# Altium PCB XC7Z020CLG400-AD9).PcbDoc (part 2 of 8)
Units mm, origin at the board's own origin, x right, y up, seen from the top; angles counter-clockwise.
Board outline 38 x 38 mm, 14 copper layers (Top Layer, GND02, ART03, PWR04, ART05, GND06, ART07, ART08, PWR09, ART10, GND11, ART12, PWR13, Bottom Layer); 276 components, 302 nets, 1684 pads, 1576 vias.
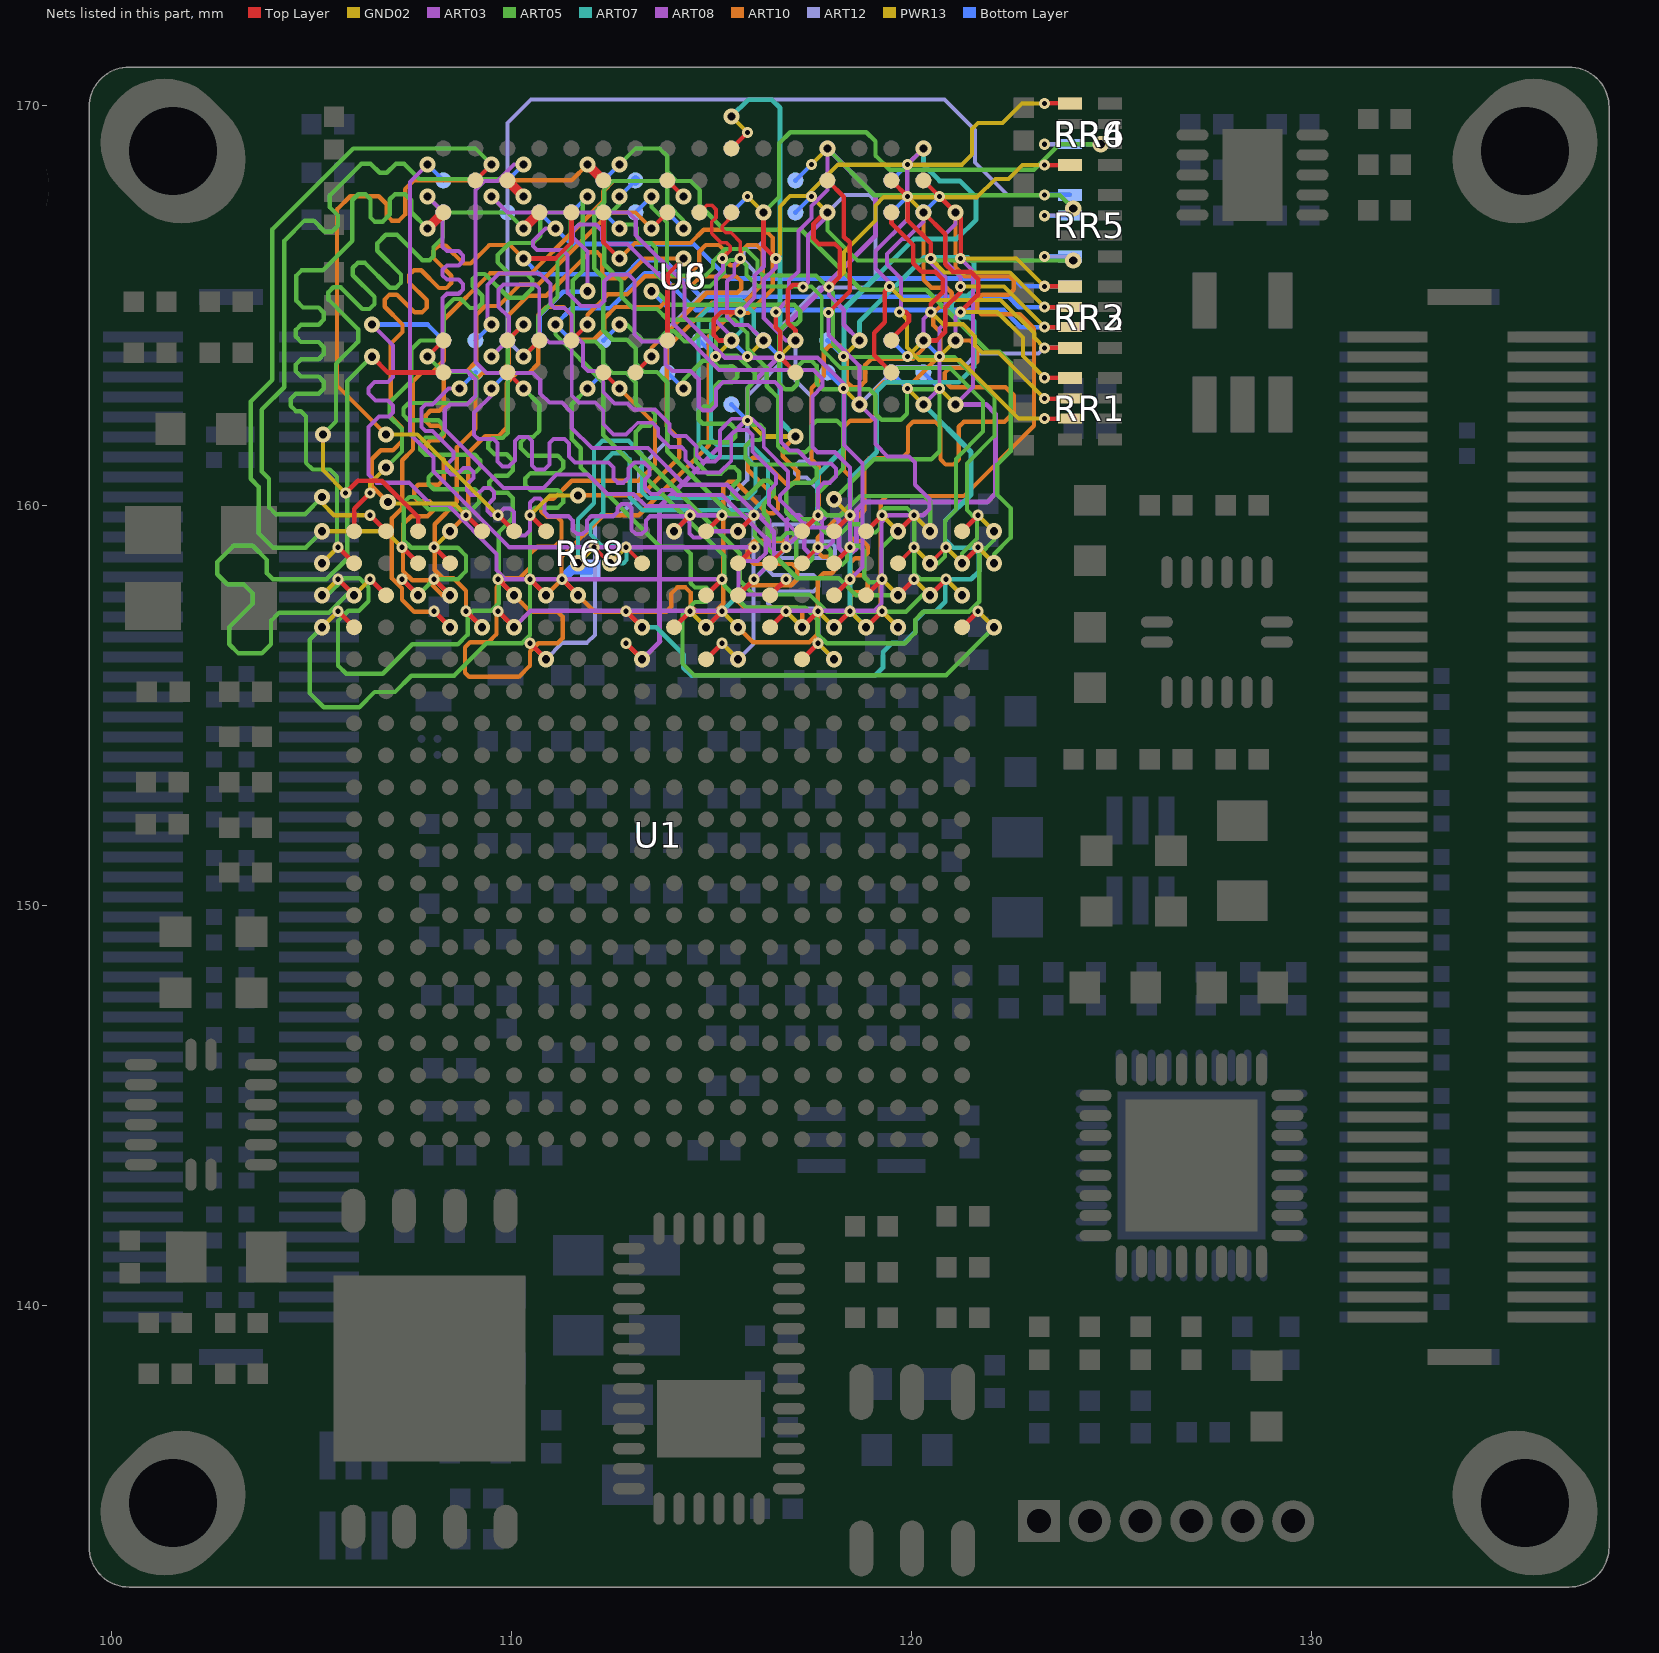
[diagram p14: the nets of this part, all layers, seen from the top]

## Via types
v1: diameter 0.406, hole 0.203, GND02 to PWR13, 466 vias
v2: diameter 0.279, hole 0.127, Top Layer to GND02, tented top, 373 vias
v3: diameter 0.406, hole 0.203, Top Layer to Bottom Layer, 324 vias
v4: diameter 0.279, hole 0.127, PWR13 to Bottom Layer, 207 vias
v5: diameter 0.279, hole 0.127, Top Layer to ART03, tented top, 41 vias
v6: diameter 0.279, hole 0.127, Top Layer to ART03, 40 vias
v7: diameter 0.279, hole 0.127, PWR13 to Bottom Layer, tented bottom, 39 vias
v8: diameter 0.279, hole 0.127, ART12 to Bottom Layer, 30 vias
v9: diameter 0.279, hole 0.127, Top Layer to GND02, 20 vias
v10: diameter 0.406, hole 0.203, Top Layer to Bottom Layer, tented both sides, 16 vias
v11: diameter 0.406, hole 0.203, ART03 to ART12, 11 vias
v12: diameter 0.406, hole 0.203, Top Layer to Bottom Layer, tented top, 9 vias

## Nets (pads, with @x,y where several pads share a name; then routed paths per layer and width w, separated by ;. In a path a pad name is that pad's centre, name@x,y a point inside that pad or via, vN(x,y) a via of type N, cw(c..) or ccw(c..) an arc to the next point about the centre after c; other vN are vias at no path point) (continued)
ADDR3-A6: RR3.6 U1.L4 U6.R8 U8.R8 | length 29.1
  Top Layer w0.114: v2(112.865,157.365) v1(113.265,156.965) ; U8.R8@119.5,168.135 119.91,167.725 119.91,167.135 120.482,166.563 v5(120.482,166.184) ; v6(123.325,164.969) RR3.6@123.96,164.969
  ART03 w0.102: v1(120.3,162.535) 120.701,162.936 120.701,164.434 120.846,164.58 120.846,165.716 120.482,166.081 v5(120.482,166.184)
  GND02 w0.102: v5(120.482,166.184) 120.829,165.837 122.457,165.837 v6(123.325,164.969)
  GND02 w0.109: v2(112.865,157.365) v1(113.265,156.965)
  ART07 w0.119: v1(113.265,156.965) 113.621,156.965 114.3,156.286 114.3,155.956 114.503,155.753 119.082,155.753 119.285,155.956 119.285,156.344 119.514,156.573 119.819,156.573 120.098,156.852 120.098,157.131 120.327,157.36 120.606,157.36 120.846,157.601 120.846,158.064 120.948,158.166 121.488,158.166 121.691,158.369 121.691,158.801 121.539,158.953 121.05,158.953 120.846,159.156 120.846,159.639 121.488,160.281 121.488,161.347 v1(120.3,162.535)
  PWR13 w0.114: v7(119.9,162.935) v1(120.3,162.535)
  Bottom Layer w0.114: U6.R8@119.5,163.335 v7(119.9,162.935)
ADDR3-A7: RR3.8 U1.K4 U6.R2 U8.R2 | length 30.3
  Top Layer w0.114: U1.K4@114.065,156.965 v2(114.465,157.365) ; v5(119.449,165.486) 119.329,165.365 119.329,164.592 119.068,164.331 119.068,163.767 U8.R2@119.5,163.335 ; v6(123.325,163.949) RR3.8@123.96,163.949
  ART03 w0.102: v5(119.449,165.486) 119.449,165.589 119.101,165.938 119.101,166.37 119.894,167.163 119.894,168.529 v1(120.3,168.935)
  GND02 w0.102: v5(119.449,165.486) 119.784,165.151 122.225,165.151 123.07,164.306 123.07,164.204 v6(123.325,163.949)
  GND02 w0.109: v2(114.465,157.365) v1(114.865,156.965)
  ART07 w0.119: v1(114.865,156.965) 117.653,159.753 117.653,160.782 118.313,161.442 118.313,164.922 120.066,166.675 121.133,166.675 121.615,167.157 121.615,167.716 121.209,168.123 120.701,168.123 120.3,168.523 v1(120.3,168.935)
  PWR13 w0.114: v7(119.9,168.535) v1(120.3,168.935)
  Bottom Layer w0.114: U6.R2@119.5,168.135 v7(119.9,168.535)
ADDR3-A8: RR3.5 U1.K1 U6.T8 U8.T8 | length 28
  Top Layer w0.114: v1(114.065,159.365) v2(114.465,159.765) ; U8.T8@120.3,168.135 121.227,167.207 v5(121.227,166.184) ; v6(123.325,165.489) RR3.5@123.96,165.489
  ART03 w0.102: v1(121.1,162.535) 121.539,162.974 121.539,165.873 v5(121.227,166.184)
  GND02 w0.102: v1(114.065,159.365) v2(114.465,159.765) ; v5(121.227,166.184) 122.63,166.184 v6(123.325,165.489)
  ART08 w0.119: v1(114.065,159.365) v2(114.465,159.765) 116.313,159.766 116.444,159.635 116.444,158.945 116.575,158.814 116.75,158.814 116.881,158.945 116.881,159.635 117.012,159.766 117.186,159.766 117.318,159.635 117.318,158.945 117.449,158.814 117.623,158.814 117.754,158.945 117.754,159.635 117.885,159.766 118.06,159.766 118.191,159.635 118.191,158.945 118.322,158.814 118.497,158.814 118.628,158.945 118.628,159.903 118.821,160.096 121.895,160.096 122.098,160.299 122.098,162.306 121.869,162.535 v1(121.1,162.535)
  PWR13 w0.114: v7(120.7,162.935) v1(121.1,162.535)
  Bottom Layer w0.114: U6.T8@120.3,163.335 v7(120.7,162.935)
ADDR3-A9: RR1.7 U1.J4 U6.R3 U8.R3 | length 28.6
  Top Layer w0.114: U1.J4@114.865,156.965 v2(115.265,157.365) ; U8.R3@119.5,164.135 119.5,164.179 119.939,164.617 119.939,164.77 119.858,164.851 v5(119.703,164.851) ; v6(123.325,162.183) RR1.7@123.96,162.183
  ART03 w0.102: v5(119.703,164.851) 119.742,164.889 119.742,165.684 119.386,166.04 119.386,166.3 119.761,166.675 119.863,166.675 120.3,167.112 v1(120.3,167.335)
  ART10 w0.109: v1(115.665,156.965) 116.039,156.591 117.45,156.591 117.653,156.794 117.653,158.166 117.805,158.318 118.008,158.318 118.11,158.42 118.11,158.623 118.008,158.725 117.78,158.725 117.653,158.852 117.653,159.207 118.466,160.02 118.466,160.731 118.313,160.884 118.313,161.976 118.466,162.128 118.974,162.128 119.101,162.255 119.101,162.89 119.304,163.093 120.04,163.093 120.719,163.772 120.719,164.345 120.548,164.516 120.548,164.821 120.701,164.973 120.879,164.973 121.006,165.1 121.006,165.329 120.879,165.456 120.498,165.456 120.3,165.653 v1(120.3,167.335)
  GND02 w0.102: v5(119.703,164.851) 119.888,164.666 119.888,163.957 120.193,163.652 121.209,163.652 122.678,162.183 v6(123.325,162.183)
  GND02 w0.109: v2(115.265,157.365) v1(115.665,156.965)
  PWR13 w0.114: v7(119.9,167.735) v1(120.3,167.335)
  Bottom Layer w0.114: U6.R3@119.5,167.335 v7(119.9,167.735)
ADDR3-A10: RR4.5 U1.F5 U6.L7 U8.L7 | length 32.7
  Top Layer w0.114: U8.L7@116.3,167.335 116.3,166.492 v5(116.608,166.184) ; U1.F5@117.265,156.165 v2(117.665,156.565) ; v6(123.325,170.061) RR4.5@123.96,170.061
  ART03 w0.102: v5(116.608,166.184) 116.608,165.961 116.307,165.659 116.307,164.694 116.865,164.135 v1(117.1,164.135)
  ART12 w0.102: v1(117.1,164.135) 117.1,163.138 117.5,162.738 117.5,161.214 117.399,161.112 117.196,161.112 117.094,161.011 117.094,160.807 117.196,160.706 117.373,160.706 117.678,160.401 117.678,159.664 117.545,159.531 116.534,159.531 116.408,159.405 116.408,159.238 116.534,159.112 117.951,159.112 118.085,158.979 118.085,158.801 117.977,158.693 116.534,158.693 116.408,158.567 116.408,158.399 116.534,158.274 117.552,158.274 117.678,158.148 117.678,157.98 117.552,157.855 116.534,157.855 116.408,157.729 116.408,157.561 116.534,157.436 117.552,157.436 117.678,157.31 117.678,156.552 v1(118.065,156.165)
  GND02 w0.102: v5(116.608,166.184) 116.713,166.289 116.713,167.488 116.967,167.742 117.373,167.742 118.161,168.529 121.26,168.529 121.514,168.783 121.514,169.418 121.666,169.57 122.276,169.57 122.766,170.061 v6(123.325,170.061)
  GND02 w0.109: v2(117.665,156.565) v1(118.065,156.165)
  PWR13 w0.114: v7(116.7,163.735) v1(117.1,164.135)
  Bottom Layer w0.114: U6.L7@116.3,164.135 v7(116.7,163.735)
ADDR3-A11: RR1.6 U1.G4 U6.R7 U8.R7 | length 27.3
  Top Layer w0.114: U1.G4@116.465,156.965 v2(116.865,157.365) ; U8.R7@119.5,167.335 119.5,167.063 120.04,166.522 120.04,166.065 120.256,165.85 120.592,165.85 120.783,165.659 120.783,165.342 120.482,165.041 v5(120.482,164.851) ; v6(123.325,162.683) RR1.6@123.96,162.683
  ART03 w0.102: v1(120.3,164.135) 120.3,164.668 v5(120.482,164.851)
  ART10 w0.109: v1(117.265,156.965) 117.265,157.334 117.145,157.455 115.824,157.455 115.672,157.607 115.672,157.836 115.849,158.013 116.992,158.013 117.145,158.166 117.145,158.42 117.018,158.547 116.053,158.547 115.911,158.689 115.911,158.964 116.078,159.131 116.992,159.131 117.678,159.817 117.678,160.985 117.5,161.163 117.5,162.941 117.805,163.246 117.805,163.855 117.958,164.008 118.237,164.008 118.389,163.855 118.389,163.093 118.516,162.966 118.694,162.966 118.847,163.119 118.847,163.525 118.999,163.678 120.04,163.678 120.3,163.937 v1(120.3,164.135)
  GND02 w0.102: v5(120.482,164.851) 120.791,164.541 121.285,164.541 121.59,164.236 121.59,164.008 121.768,163.83 122.178,163.83 v6(123.325,162.683)
  GND02 w0.109: v2(116.865,157.365) v1(117.265,156.965)
  PWR13 w0.114: v7(119.9,163.735) v1(120.3,164.135)
  Bottom Layer w0.114: U6.R7@119.5,164.135 v7(119.9,163.735)
ADDR3-A12: RR4.8 U1.E4 U6.N7 U8.N7 | length 30.8
  Top Layer w0.114: U8.N7@117.9,167.335 117.83,167.335 117.551,167.056 117.551,166.675 117.678,166.548 118.085,166.548 118.212,166.421 118.212,165.738 v5(117.942,165.469) ; U1.E4@118.065,156.965 v2(118.465,157.365) ; v6(123.325,168.521) RR4.8@123.96,168.521
  ART03 w0.102: v5(117.942,165.469) 117.942,165.268 118.306,164.904 118.306,164.528 v1(118.7,164.135)
  GND02 w0.102: v5(117.942,165.469) 118.313,165.84 118.313,166.345 119.101,167.132 119.101,167.513 119.304,167.716 121.641,167.716 122.098,168.173 122.428,168.173 122.776,168.521 v6(123.325,168.521)
  GND02 w0.109: v2(118.465,157.365) v1(118.865,156.965)
  ART07 w0.119: v1(118.7,164.135) 118.7,164.598 120.32,166.218 121.412,166.218 121.564,166.065 121.564,165.405 121.412,165.252 121.183,165.252 121.006,165.075 121.006,164.897 121.183,164.719 121.463,164.719 121.564,164.617 121.564,163.474 121.183,163.093 119.361,163.093 119.132,162.865 119.132,161.347 118.466,160.68 118.466,157.364 v1(118.865,156.965)
  PWR13 w0.114: v7(118.3,163.735) v1(118.7,164.135)
  Bottom Layer w0.114: U6.N7@117.9,164.135 v7(118.3,163.735)
ADDR3-A13: RR3.7 U1.D4 U6.T3 U8.T3 | length 25.9
  Top Layer w0.114: U1.D4@118.865,156.965 v2(119.265,157.365) ; U8.T3@120.3,164.135 120.625,164.135 120.846,164.357 120.846,164.961 121.227,165.342 v5(121.227,165.486) ; v6(123.325,164.469) RR3.7@123.96,164.469
  ART03 w0.102: v1(121.1,167.335) 121.1,167.049 120.846,166.795 120.846,166.104 121.227,165.723 v5(121.227,165.486)
  ART10 w0.109: v1(119.665,156.965) 119.228,157.402 119.228,160.096 119.38,160.249 121.31,160.249 123.063,162.001 123.063,164.44 122.707,164.795 121.742,164.795 121.641,164.897 121.641,165.151 121.768,165.278 122.428,165.278 122.555,165.405 122.555,165.633 122.453,165.735 121.336,165.735 121.1,165.971 v1(121.1,167.335)
  GND02 w0.102: v5(121.227,165.486) 122.309,165.486 v6(123.325,164.469)
  GND02 w0.109: v2(119.265,157.365) v1(119.665,156.965)
  PWR13 w0.114: v7(120.7,167.735) v1(121.1,167.335)
  Bottom Layer w0.114: U6.T3@120.3,167.335 v7(120.7,167.735)
ADDR3-A14: RR1.5 U1.F4 U6.T7 U8.T7 | length 26.7
  Top Layer w0.114: U1.F4@117.265,156.965 v2(117.665,157.365) ; U8.T7@120.3,167.335 120.846,166.789 120.846,166.04 121.037,165.85 121.481,165.85 121.672,165.659 121.672,165.295 v5(121.227,164.851) ; v6(123.325,163.203) RR1.5@123.96,163.203
  ART03 w0.102: v1(121.1,164.135) 121.1,164.723 v5(121.227,164.851)
  ART10 w0.109: v1(118.065,156.965) 118.466,157.366 118.466,157.713 118.594,157.841 118.782,157.841 118.91,157.969 118.91,158.139 118.782,158.267 118.594,158.267 118.466,158.395 118.466,158.566 118.594,158.694 118.782,158.694 118.91,158.822 118.91,158.993 118.782,159.121 118.594,159.121 118.466,159.249 118.466,159.537 118.821,159.893 118.821,161.061 118.948,161.188 119.761,161.188 119.913,161.341 119.913,161.976 120.04,162.103 120.599,162.103 120.726,161.976 120.726,161.163 120.853,161.036 121.056,161.036 121.183,161.163 121.183,161.976 121.31,162.103 122.326,162.103 122.555,162.331 122.555,162.763 122.352,162.966 120.98,162.966 120.828,163.119 120.828,163.322 120.955,163.449 121.488,163.449 121.641,163.601 121.641,163.957 121.463,164.135 v1(121.1,164.135)
  GND02 w0.102: v5(121.227,164.851) 122.144,164.851 122.784,164.211 122.784,163.744 v6(123.325,163.203)
  GND02 w0.109: v2(117.665,157.365) v1(118.065,156.965)
  PWR13 w0.114: v7(120.7,163.735) v1(121.1,164.135)
  Bottom Layer w0.114: U6.T7@120.3,164.135 v7(120.7,163.735)
ADDR3-BA0: RR5.7 U1.L5 U6.M2 U8.M2 | length 32.5
  Top Layer w0.114: v2(112.865,156.565) v1(113.265,156.165) ; v5(116.608,164.851) 116.608,164.468 116.719,164.357 116.719,163.716 U8.M2@117.1,163.335
  ART03 w0.102: v5(116.608,164.851) 116.942,165.184 116.942,165.633 117.17,165.862 117.17,166.872 117.5,167.202 117.5,167.494 117.9,167.894 v1(117.9,168.935)
  ART05 w0.109: v1(117.9,168.935) 119.068,167.767 123.711,167.767 v11(124.046,167.433)
  ART12 w0.102: v8(123.325,167.255) 123.868,167.255 v11(124.046,167.433)
  GND02 w0.109: v2(112.865,156.565) v1(113.265,156.165)
  ART08 w0.119: v1(113.265,156.165) 113.716,156.616 113.7,156.632 113.7,159.979 115.9,162.179 115.9,162.941 116.713,163.754 116.713,164.363 119.101,166.751 119.101,167.734 v1(117.9,168.935)
  PWR13 w0.114: v7(117.5,168.535) v1(117.9,168.935)
  Bottom Layer w0.114: U6.M2@117.1,168.135 v7(117.5,168.535) ; v8(123.325,167.255) RR5.7@123.96,167.255
ADDR3-BA1: RR2.5 U1.R4 U6.N8 U8.N8 | length 30.9
  Top Layer w0.114: v2(109.665,157.365) v1(110.065,156.965) ; U8.N8@117.9,168.135 118.306,167.729 118.306,166.732 118.453,166.586 118.453,165.361 v5(117.925,164.834)
  ART03 w0.102: v1(110.065,156.965) 110.478,157.378 119.075,157.378 119.253,157.556 119.253,159.588 119.431,159.766 120.294,159.766 120.447,159.918 120.447,160.172 120.091,160.528 120.091,161.087 119.939,161.239 119.405,161.239 119.101,161.544 119.101,162.134 v1(118.7,162.535) 118.7,163.494 117.925,164.269 v5(117.925,164.834)
  ART12 w0.102: v1(118.7,162.535) 119.639,163.474 121.31,163.474 121.641,163.805 123.181,163.805 v8(123.325,163.949)
  GND02 w0.109: v2(109.665,157.365) v1(110.065,156.965)
  PWR13 w0.114: v7(118.3,162.935) v1(118.7,162.535)
  Bottom Layer w0.114: U6.N8@117.9,163.335 v7(118.3,162.935) ; v8(123.325,163.949) RR2.5@123.96,163.949
ADDR3-BA2: RR5.5 U1.J5 U6.M3 U8.M3 | length 30.2
  Top Layer w0.114: U1.J5@114.865,156.165 v2(115.265,156.565) ; U8.M3@117.1,164.135 117.1,164.389 116.909,164.58 116.909,165.398 117.043,165.532 117.227,165.532 v5(117.29,165.469)
  ART03 w0.102: v5(117.29,165.469) 117.413,165.591 117.413,165.986 117.411,165.987 117.411,166.764 117.9,167.252 v1(117.9,167.335)
  ART05 w0.109: v1(117.9,167.335) 117.9,166.885 118.651,166.133 v11(124.046,166.133)
  ART12 w0.102: v1(115.665,156.165) 116.053,156.553 116.053,159.766 115.926,159.893 115.57,159.893 115.443,160.02 115.443,160.198 115.893,160.648 115.893,162.738 116.713,163.557 116.713,164.465 117.704,165.456 118.847,165.456 119.101,165.71 119.101,167.615 118.948,167.767 118.332,167.767 v1(117.9,167.335) ; v8(123.325,166.235) 123.944,166.235 v11(124.046,166.133)
  GND02 w0.109: v2(115.265,156.565) v1(115.665,156.165)
  PWR13 w0.114: v7(117.5,167.735) v1(117.9,167.335)
  Bottom Layer w0.114: U6.M3@117.1,167.335 v7(117.5,167.735) ; v8(123.325,166.235) RR5.5@123.96,166.235
ADDR3-CAS: RR6.6 U1.P5 U6.K3 U8.K3 | length 34.6
  Top Layer w0.114: v2(110.465,156.565) v1(110.865,156.165) ; U8.K3@115.5,164.135 115.189,164.135 115.062,164.262 115.062,164.668 115.24,164.846 115.715,164.846 v5(115.719,164.851)
  ART03 w0.102: v5(115.719,164.851) 116.074,165.205 116.074,165.757 116.307,165.989 116.307,167.328 v1(116.3,167.335)
  ART05 w0.109: v1(116.3,167.335) 116.688,167.723 116.688,169.062 116.967,169.342 118.872,169.342 119.101,169.113 119.101,168.758 119.456,168.402 123.063,168.402 123.702,169.041 v11(124.731,169.041)
  ART12 w0.102: v1(110.865,156.165) 111.278,156.579 111.893,156.579 112.083,156.769 112.083,159.607 112.243,159.766 112.7,159.766 113.192,160.258 113.192,160.925 113.9,161.634 113.9,164.428 114.801,165.329 115.926,165.329 116.078,165.481 116.078,165.862 115.799,166.141 115.799,166.345 115.926,166.472 116.154,166.472 116.3,166.617 v1(116.3,167.335) ; v8(123.325,169.041) v11(124.731,169.041)
  GND02 w0.109: v2(110.465,156.565) v1(110.865,156.165)
  PWR13 w0.114: v7(115.9,167.735) v1(116.3,167.335)
  Bottom Layer w0.114: U6.K3@115.5,167.335 v7(115.9,167.735) ; v8(123.325,169.041) RR6.6@123.96,169.041
ADDR3-CKE0: R68.1 U1.N3 U6.K9 U8.K9 | length 29.3
  Top Layer w0.114: v2(111.265,158.165) v1(111.665,157.765) ; U8.K9@115.5,168.935 v2(115.9,169.335)
  ART10 w0.109: v1(111.665,157.765) 112.077,157.353 113.868,157.353 113.995,157.48 113.995,157.81 114.148,157.963 114.351,157.963 114.478,157.836 114.478,157.505 114.63,157.353 115.087,157.353 115.291,157.556 115.291,160.464 115.427,160.601 115.608,160.601 116.392,159.817 116.561,159.817 116.662,159.918 116.662,160.15 115.91,160.902 115.91,161.083 116.03,161.204 116.211,161.204 116.862,160.553 117.043,160.553 117.17,160.68 117.17,160.849 116.782,161.236 116.782,161.417 v1(117.1,161.735)
  GND02 w0.109: v2(111.265,158.165) v1(111.665,157.765) ; v1(115.5,169.735) v2(115.9,169.335)
  ART07 w0.119: v1(115.5,169.735) 115.92,170.155 116.51,170.155 116.713,169.951 116.713,162.122 v1(117.1,161.735)
  PWR13 w0.114: v2(111.265,158.165) v1(111.665,157.765) ; v7(115.9,162.135) 116.3,161.735 v1(117.1,161.735)
  Bottom Layer w0.114: U6.K9@115.5,162.535 v7(115.9,162.135)
  Bottom Layer w0.254: v2(111.265,158.165) 111.508,158.408 R68.1@111.973,158.408
  other v4: 111.265,158.165
ADDR3-CLK0_N: U1.M2 U6.K7 U8.K7 | length 22.8
  Top Layer w0.089: v2(112.065,158.965) U1.M2@112.465,158.565 ; U8.K7@115.5,167.335 115.5,167.229 115.265,166.994 115.265,166.917 115.353,166.83 115.491,166.83 115.722,166.599 115.722,166.187 v5(115.719,166.184)
  ART03 w0.097: v5(115.719,166.184) 115.57,166.035 115.57,165.786 115.392,165.608 115.392,164.719 115.592,164.52 115.915,164.52 v1(116.3,164.135)
  GND02 w0.109: v1(111.665,158.565) v2(112.065,158.965)
  ART07 w0.107: v1(111.665,158.565) 111.665,159.664 112.065,160.064 112.065,161.422 112.268,161.625 112.93,161.625 113.264,161.291 113.264,160.345 113.411,160.198 115.926,160.198 116.103,160.376 116.103,160.985 115.875,161.214 115.005,161.214 114.676,161.543 114.676,164.684 115.148,165.156 115.724,165.156 116.058,164.822 116.058,164.377 v1(116.3,164.135)
  PWR13 w0.114: v7(115.9,163.735) v1(116.3,164.135)
  Bottom Layer w0.089: U6.K7@115.5,164.135 v7(115.9,163.735)
ADDR3-CLK0_P: U1.L2 U6.J7 U8.J7 | length 22.9
  Top Layer w0.089: v2(112.865,158.965) U1.L2@113.265,158.565 ; U8.J7@114.7,167.335 114.878,167.513 115.011,167.513 115.113,167.411 115.113,167.204 115.009,167.1 115.009,166.811 115.246,166.573 115.385,166.573 115.466,166.492 115.466,166.375 v5(115.275,166.184)
  ART03 w0.097: v5(115.275,166.184) 115.291,166.168 115.291,165.902 115.113,165.724 115.113,164.617 115.5,164.23 v1(115.5,164.135)
  GND02 w0.109: v1(112.465,158.565) v2(112.865,158.965)
  ART07 w0.107: v1(112.465,158.565) 112.794,158.565 112.878,158.648 112.878,158.877 112.751,159.004 112.254,159.004 111.975,159.283 111.975,159.512 112.293,159.831 112.293,161.087 112.522,161.315 112.801,161.315 112.954,161.163 112.954,160.217 113.283,159.888 116.054,159.888 116.413,160.247 116.413,161.114 116.003,161.524 115.133,161.524 114.986,161.671 114.986,164.555 115.277,164.846 115.595,164.846 115.748,164.694 115.748,164.383 v1(115.5,164.135)
  PWR13 w0.114: v7(115.1,163.735) v1(115.5,164.135)
  Bottom Layer w0.089: U6.J7@114.7,164.135 v7(115.1,163.735)
ADDR3-D0: U1.C3 U6.E3 | length 19.5
  Top Layer w0.114: U1.C3@119.665,157.765 v2(120.065,158.165)
  ART05 w0.109: v3(111.9,167.735) 111.785,167.62 111.785,165.887 111.531,165.633 111.531,164.313 111.735,164.109 112.1,164.109 112.293,163.916 112.293,163.551 112.522,163.322 112.878,163.322 113.106,163.093 113.106,162.56 113.259,162.408 113.487,162.408 113.589,162.306 113.589,162.128 113.462,162.001 113.259,162.001 113.106,161.849 113.106,161.416 115.705,158.817 115.705,158.133 116.053,157.785 117.45,157.785 117.881,157.353 119.863,157.353 120.275,157.765 v1(120.465,157.765)
  GND02 w0.109: v2(120.065,158.165) v1(120.465,157.765)
  Bottom Layer w0.114: U6.E3@111.5,167.335 v3(111.9,167.735)
ADDR3-D1: U1.B3 U6.F7 | length 19.5
  Top Layer w0.114: U1.B3@120.465,157.765 v2(120.865,158.165)
  ART05 w0.109: v3(112.7,164.535) 112.884,164.535 113.284,164.135 113.665,164.135 113.894,164.363 114.071,164.363 114.325,164.109 114.503,164.109 114.757,164.363 114.96,164.363 115.113,164.211 115.113,163.932 115.291,163.754 115.646,163.754 116.078,163.322 116.078,163.119 115.9,162.941 115.9,162.154 116.027,162.027 116.205,162.027 116.307,161.925 116.307,161.747 116.205,161.646 116.002,161.646 115.849,161.493 115.849,161.188 116.002,161.036 117.526,161.036 117.627,160.934 117.627,160.706 117.5,160.579 117.043,160.579 116.865,160.401 116.865,159.842 117.043,159.664 117.526,159.664 117.881,159.309 118.237,159.309 118.471,159.542 118.715,159.542 118.923,159.334 119.101,159.334 119.228,159.461 119.228,159.842 119.329,159.944 119.888,159.944 120.066,159.766 120.066,158.318 120.218,158.166 120.864,158.166 v1(121.265,157.765)
  GND02 w0.109: v2(120.865,158.165) v1(121.265,157.765)
  Bottom Layer w0.114: U6.F7@112.3,164.135 v3(112.7,164.535)
ADDR3-D2: U1.A2 U6.F2 | length 19.8
  Top Layer w0.114: U1.A2@121.265,158.565 v2(121.665,158.965)
  ART05 w0.109: v3(112.7,168.535) 113.1,168.935 113.703,168.935 113.894,168.744 113.894,168.351 114.122,168.123 114.478,168.123 114.706,167.894 114.706,167.513 115.315,166.905 117.245,166.905 118.745,165.405 120.371,165.405 121.92,163.855 122.199,163.855 122.479,163.576 122.479,161.366 122.149,161.036 122.149,160.274 122.479,159.944 122.479,159.207 122.065,158.793 v1(122.065,158.565)
  GND02 w0.109: v2(121.665,158.965) v1(122.065,158.565)
  Bottom Layer w0.114: U6.F2@112.3,168.135 v3(112.7,168.535)
ADDR3-D3: U1.A4 U6.F8 | length 19.6
  Top Layer w0.114: U1.A4@121.265,156.965 v2(121.665,157.365)
  ART05 w0.109: v3(111.9,162.935) 111.506,162.541 111.506,161.671 111.735,161.442 111.735,160.96 113.716,158.979 114.3,158.979 114.478,158.801 114.478,158.068 114.587,157.959 114.877,157.959 114.986,157.85 114.986,157.705 114.877,157.596 114.587,157.596 114.275,157.283 114.275,156.058 114.562,155.77 120.87,155.77 v1(122.065,156.965)
  GND02 w0.109: v2(121.665,157.365) v1(122.065,156.965)
  Bottom Layer w0.114: v3(111.9,162.935) U6.F8@112.3,163.335
ADDR3-D4: U1.D3 U6.H3 | length 19.8
  Top Layer w0.114: U1.D3@118.865,157.765 v2(119.265,158.165)
  ART05 w0.109: v3(114.3,166.935) 114.3,167.132 113.894,167.538 113.894,167.97 113.741,168.123 112.522,168.123 112.319,167.919 112.319,167.589 112.065,167.335 112.065,165.938 112.293,165.71 112.293,164.389 112.53,164.152 112.886,164.152 113.106,163.932 113.106,163.551 113.309,163.347 113.64,163.347 113.894,163.093 113.894,161.366 115.468,159.791 115.773,159.791 116.078,159.487 116.078,159.258 117.145,158.191 118.186,158.191 118.612,157.765 v1(119.665,157.765)
  GND02 w0.109: v2(119.265,158.165) v1(119.665,157.765)
  Bottom Layer w0.114: U6.H3@113.9,167.335 v3(114.3,166.935)
ADDR3-D5: U1.D1 U6.H8 | length 19.4
  Top Layer w0.114: U1.D1@118.865,159.365 v2(119.265,159.765)
  ART05 w0.109: v3(114.3,162.935) 114.3,163.144 114.783,163.627 115.037,163.627 115.189,163.474 115.545,163.474 115.646,163.373 115.646,163.22 115.519,163.093 115.189,163.093 115.087,162.992 115.087,162.611 114.96,162.484 114.808,162.484 114.681,162.357 114.681,162.154 114.783,162.052 115.468,162.052 115.595,161.925 115.595,161.722 115.468,161.595 114.757,161.595 114.605,161.442 114.605,161.112 114.91,160.807 115.237,160.807 115.392,160.962 115.575,160.962 115.697,160.84 115.697,160.657 115.521,160.481 115.521,160.298 115.643,160.175 115.826,160.175 116.28,160.63 116.434,160.63 116.561,160.503 116.561,160.299 116.307,160.045 116.307,159.817 116.408,159.715 116.408,159.309 116.535,159.182 116.738,159.182 116.878,159.321 117.03,159.321 117.119,159.233 117.119,158.648 117.221,158.547 117.399,158.547 117.526,158.674 117.526,158.852 117.678,159.004 117.856,159.004 117.983,158.877 117.983,158.623 118.085,158.521 118.262,158.521 118.389,158.648 118.389,158.852 118.542,159.004 118.694,159.004 118.821,158.877 118.821,158.217 118.948,158.09 119.126,158.09 119.253,158.217 119.253,158.953 v1(119.665,159.365)
  GND02 w0.109: v2(119.265,159.765) v1(119.665,159.365)
  Bottom Layer w0.114: U6.H8@113.9,163.335 v3(114.3,162.935)
ADDR3-D6: U1.C1 U6.G2 | length 19.7
  Top Layer w0.114: U1.C1@119.665,159.365 v2(120.065,159.765)
  ART05 w0.109: v3(112.7,167.735) 112.7,167.539 112.319,167.157 112.319,166.04 112.751,165.608 112.751,165.227 113.055,164.922 113.637,164.922 113.905,164.654 115.558,164.654 115.9,164.313 115.9,163.932 116.383,163.449 116.383,162.992 116.662,162.713 116.662,161.493 116.815,161.341 117.348,161.341 117.5,161.493 117.5,162.001 117.627,162.128 118.135,162.128 118.288,161.976 118.288,160.934 117.653,160.299 117.653,159.995 117.881,159.766 118.237,159.766 118.72,160.249 120.32,160.249 120.465,160.103 v1(120.465,159.365)
  GND02 w0.109: v2(120.065,159.765) v1(120.465,159.365)
  Bottom Layer w0.114: v3(112.7,167.735) U6.G2@113.1,168.135
ADDR3-D7: U1.E1 U6.H7 | length 19.6
  Top Layer w0.114: U1.E1@118.065,159.365 v2(118.465,159.765)
  ART05 w0.109: v3(113.5,165.365) 113.629,165.365 113.97,165.024 117.069,165.024 117.221,164.871 117.221,164.643 117.119,164.541 116.865,164.541 116.688,164.363 116.688,163.068 116.84,162.916 117.018,162.916 117.145,163.043 117.145,163.474 117.297,163.627 117.5,163.627 117.627,163.5 117.627,163.068 117.78,162.916 118.948,162.916 119.101,162.763 119.101,162.306 119.253,162.154 119.736,162.154 119.888,162.306 119.888,162.814 119.99,162.916 120.574,162.916 120.701,162.789 120.701,161.366 120.498,161.163 119.063,161.163 v1(118.065,160.165)
  GND02 w0.102: v1(118.065,160.165) v2(118.465,159.765)
  Bottom Layer w0.114: v3(113.5,165.365) 113.9,164.965 U6.H7@113.9,164.135
ADDR3-D8: U1.E2 U6.D7 | length 17.8
  Top Layer w0.114: U1.E2@118.065,158.565 v5(118.465,158.965)
  ART03 w0.102: v3(111.9,165.365) 111.9,166.357 111.531,166.726 111.531,166.878 111.684,167.03 112.116,167.03 112.268,166.878 112.268,166.675 112.395,166.548 112.903,166.548 114.046,165.405 114.046,164.541 115.189,163.398 117.551,163.398 117.78,163.17 117.78,162.992 117.526,162.738 117.526,161.468 117.653,161.341 118.085,161.341 118.465,160.96 v5(118.465,158.965)
  Bottom Layer w0.114: U6.D7@110.7,164.135 110.7,164.751 111.299,165.35 v3@111.9,165.35
ADDR3-D9: U1.E3 U6.C3 | length 17.8
  Top Layer w0.114: U1.E3@118.065,157.765 v5(118.465,158.165)
  ART03 w0.102: v3(109.5,167.735) 109.9,167.335 112.928,167.335 113.106,167.157 113.106,166.776 114.325,165.557 114.325,164.719 115.341,163.703 117.653,163.703 118.313,163.043 118.313,161.519 118.77,161.061 118.77,158.47 v5(118.465,158.165)
  Bottom Layer w0.114: v3(109.5,167.735) U6.C3@109.9,167.335
ADDR3-D10: U1.G3 U6.C8 | length 17.9
  Top Layer w0.114: U1.G3@116.465,157.765 v5(116.865,158.165)
  ART03 w0.102: v3(109.5,162.935) 109.5,162.764 109.068,162.331 109.068,161.773 109.169,161.671 109.55,161.671 109.652,161.569 109.652,161.112 109.779,160.985 109.931,160.985 110.084,161.138 110.084,161.62 110.185,161.722 110.414,161.722 110.515,161.62 110.515,161.011 110.617,160.909 110.82,160.909 110.947,161.036 110.947,161.569 111.049,161.671 111.328,161.671 111.439,161.56 111.439,161.239 111.591,161.087 112.42,161.087 112.547,160.96 112.547,160.68 112.649,160.579 112.801,160.579 112.928,160.706 112.928,160.934 113.081,161.087 113.309,161.087 113.449,160.947 113.449,160.769 113.335,160.655 113.335,160.452 113.487,160.299 113.665,160.299 113.767,160.401 113.995,160.401 114.122,160.274 115.264,160.274 116.357,159.181 116.357,158.826 116.154,158.623 115.824,158.623 115.672,158.471 115.672,157.963 115.849,157.785 116.485,157.785 v5(116.865,158.165)
  Bottom Layer w0.114: v3(109.5,162.935) U6.C8@109.9,163.335
ADDR3-D11: U1.H3 U6.C2 | length 17.9
  Top Layer w0.114: U1.H3@115.665,157.765 v5(116.065,158.165)
  ART03 w0.102: v3(110.3,168.535) 110.064,168.535 109.652,168.123 109.322,168.123 109.096,167.897 109.096,163.599 109.372,163.322 110.541,163.322 110.719,163.144 110.719,162.814 110.953,162.579 111.258,162.579 111.506,162.331 111.506,161.95 112.014,161.442 113.411,161.442 114.325,160.528 115.392,160.528 116.561,159.36 116.561,158.661 v5(116.065,158.165)
  Bottom Layer w0.114: U6.C2@109.9,168.135 v3(110.3,168.535)
ADDR3-D12: U1.J3 U6.A7 | length 17.9
  Top Layer w0.114: U1.J3@114.865,157.765 v5(115.265,158.165)
  ART03 w0.102: v3(106.515,164.535) 107.036,164.014 107.036,163.22 106.909,163.093 106.578,163.093 106.426,162.941 106.426,162.814 106.604,162.636 106.909,162.636 107.036,162.509 107.036,162.331 106.938,162.234 106.684,162.234 106.426,161.976 106.426,160.782 106.629,160.579 107.442,160.579 108.001,160.02 108.407,160.02 109.626,158.801 109.626,158.394 109.856,158.165 v5(115.265,158.165)
  Bottom Layer w0.114: v3@106.502,164.535 v3(106.515,164.535) 107.9,164.535 U6.A7@108.3,164.135
ADDR3-D13: U1.H2 U6.A2 | length 18
  Top Layer w0.114: U1.H2@115.665,158.565 v5(116.065,158.965)
  ART03 w0.102: v3(107.9,168.535) 107.467,168.102 107.467,161.798 108.053,161.212 108.053,160.857 109.945,158.965 v5(116.065,158.965)
  Bottom Layer w0.114: v3(107.9,168.535) U6.A2@108.3,168.135
ADDR3-D14: U1.H1 U6.B8 | length 17.9
  Top Layer w0.114: v1(115.665,159.365) v2(116.065,159.765)
  ART03 w0.102: v3(108.7,162.935) 108.427,162.935 108.026,162.535 107.848,162.535 107.747,162.433 107.747,161.976 107.848,161.874 108.026,161.874 108.553,161.348 108.553,161.197 108.389,161.033 108.389,160.882 108.49,160.782 108.641,160.782 108.804,160.945 108.955,160.945 109.056,160.845 109.056,160.694 108.892,160.53 108.892,160.38 108.993,160.279 109.144,160.279 109.307,160.442 109.458,160.442 109.559,160.342 109.559,160.191 109.395,160.027 109.395,159.877 109.496,159.776 109.647,159.776 109.81,159.939 109.961,159.939 110.058,159.842 110.058,159.385 110.185,159.258 110.338,159.258 110.465,159.385 110.465,160.078 110.571,160.185 110.714,160.185 110.82,160.078 110.82,159.847 110.927,159.741 111.425,159.741 111.531,159.634 111.531,159.403 111.638,159.296 111.78,159.296 111.887,159.403 111.887,159.634 111.994,159.741 112.542,159.741 112.649,159.847 112.649,159.943 112.756,160.049 112.898,160.049 113.005,159.943 113.005,159.403 113.111,159.296 113.254,159.296 113.36,159.403 113.36,159.634 113.467,159.741 114.3,159.741 114.452,159.588 114.452,159.309 114.554,159.207 114.732,159.207 114.89,159.365 v1(115.665,159.365)
  GND02 w0.102: v1(115.665,159.365) v2(116.065,159.765)
  Bottom Layer w0.114: v3(108.7,162.935) U6.B8@109.1,163.335
ADDR3-D15: U1.J1 U6.A3 | length 17.9
  Top Layer w0.114: U1.J1@114.865,159.365 v5(115.265,159.765)
  ART03 w0.102: v3(107.9,167.735) 108.28,167.355 108.28,166.477 108.387,166.37 108.682,166.37 108.788,166.263 108.788,166.121 108.682,166.014 108.387,166.014 108.28,165.908 108.28,165.765 108.387,165.659 108.682,165.659 108.788,165.552 108.788,165.41 108.682,165.303 108.387,165.303 108.28,165.197 108.28,163.525 108.43,163.376 108.887,163.376 109.099,163.164 109.099,162.744 108.89,162.535 108.458,162.535 108.331,162.408 108.331,161.925 109.804,160.452 110.795,160.452 111.125,160.782 111.912,160.782 112.395,160.299 113.055,160.299 113.361,159.994 114.428,159.994 114.657,159.765 v5(115.265,159.765)
  Bottom Layer w0.114: v3(107.9,167.735) U6.A3@108.3,167.335
ADDR3-D16: U1.P1 U8.E3 | length 18.5
  Top Layer w0.114: v2(110.465,159.765) U1.P1@110.865,159.365 ; U8.E3@111.5,164.135 v3(111.9,164.535)
  ART10 w0.109: v1(111.665,160.262) 113.246,160.262 114.198,161.214 114.198,161.671 113.878,161.991 113.878,163.941 115.011,165.075 115.799,165.075 116.281,165.557 116.281,166.37 116.129,166.522 115.9,166.522 115.748,166.37 115.748,166.141 115.621,166.014 115.468,166.014 115.341,166.141 115.341,166.37 115.189,166.522 114.859,166.522 114.692,166.355 114.692,166.05 114.381,165.74 113.339,165.74 112.888,165.288 112.41,165.288 111.9,164.778 v3(111.9,164.535)
  GND02 w0.102: v2(110.465,159.765) 110.962,160.262 v1(111.665,160.262)
ADDR3-D17: U1.P3 U8.F7 | length 18.7
  Top Layer w0.114: v2(110.465,158.165) v1(110.865,157.765) ; U8.F7@112.3,167.335 112.3,166.584 v3(112.7,166.184)
  ART10 w0.109: v1(110.865,157.765) 111.252,158.152 111.252,158.725 112.293,159.766 113.182,159.766 114.935,161.519 114.935,164.236 115.519,164.821 115.926,164.821 116.535,165.43 116.535,166.7 116.332,166.903 114.808,166.903 114.478,166.573 113.089,166.573 v3(112.7,166.184)
  GND02 w0.109: v2(110.465,158.165) v1(110.865,157.765)
ADDR3-D18: U1.R3 U8.F2 | length 18.6
  Top Layer w0.114: v2(109.665,158.165) v1(110.065,157.765) ; U8.F2@112.3,163.335 v3(112.7,162.935)
  ART10 w0.109: v1(110.065,157.765) 110.477,157.353 111.15,157.353 111.277,157.226 111.277,156.693 111.15,156.566 110.668,156.566 110.465,156.362 110.465,156.007 110.185,155.727 108.941,155.727 108.839,155.829 108.839,156.464 108.966,156.591 109.423,156.591 109.627,156.795 109.627,157.963 109.855,158.191 110.203,158.191 110.465,158.453 110.465,158.801 110.642,158.979 111.074,158.979 111.252,159.156 111.252,159.614 111.141,159.724 110.887,159.724 110.744,159.868 110.744,160.02 110.896,160.172 111.049,160.172 111.506,160.63 113.182,160.63 113.589,161.036 113.589,162.046 v3(112.7,162.935)
  GND02 w0.109: v2(109.665,158.165) v1(110.065,157.765)
ADDR3-D19: U1.R1 U8.F8 | length 18.7
  Top Layer w0.114: v2(109.665,159.765) U1.R1@110.065,159.365
  Top Layer w0.254: v3(111.9,168.535) U8.F8@112.3,168.135
  ART10 w0.109: v1(106.865,161.786) 105.639,163.012 105.639,167.411 105.969,167.742 106.68,167.742 106.883,167.538 106.883,167.259 107.01,167.132 107.188,167.132 107.34,167.284 107.34,167.919 107.562,168.141 111.506,168.141 v3(111.9,168.535)
  GND02 w0.102: v1(106.865,161.786) 107.645,161.786 v2(109.665,159.765)
ADDR3-D20: U1.T4 U8.H3 | length 18.6
  Top Layer w0.114: v2(108.865,157.365) v1(109.265,156.965) ; U8.H3@113.9,164.135 113.9,165.784 v3(114.3,166.184)
  ART10 w0.109: v1(109.265,156.965) v2(108.865,157.365) 108.864,157.877 108.551,158.191 108.28,158.191 108.083,158.388 108.083,159.543 108.636,160.096 108.636,161.462 109.099,161.925 109.099,163.144 109.277,163.322 109.703,163.322 109.931,163.551 109.931,164.77 110.414,165.252 110.871,165.252 111.963,166.345 112.141,166.345 112.268,166.218 112.268,165.786 112.37,165.684 112.827,165.684 113.327,166.184 v3(114.3,166.184)
  GND02 w0.109: v2(108.865,157.365) v1(109.265,156.965)
ADDR3-D21: U1.U4 U8.H8 | length 18.7
  Top Layer w0.114: v2(108.065,157.365) v1(108.465,156.965) ; U8.H8@113.9,168.135 v3(114.3,167.735)
  ART10 w0.109: v1(108.465,156.965) 108.077,157.353 107.565,157.353 107.264,157.654 107.264,157.937 107.01,158.191 107.01,159.69 107.27,159.949 107.27,161.143 107.538,161.411 107.538,163.113 107.747,163.322 107.999,163.322 108.306,163.629 108.306,164.652 109.464,165.811 110.488,165.811 111.555,166.878 111.557,166.878 112.293,167.615 112.293,167.869 112.547,168.123 113.912,168.123 v3(114.3,167.735)
  GND02 w0.109: v2(108.065,157.365) v1(108.465,156.965)
ADDR3-D22: U1.U2 U8.G2 | length 18.4
  Top Layer w0.114: v2(108.065,158.965) U1.U2@108.465,158.565 ; U8.G2@113.1,163.335 v3(113.5,163.735)
  ART10 w0.109: v1(108.465,159.365) 108.915,159.815 108.915,161.315 109.347,161.747 109.674,161.747 109.877,161.95 109.877,163.068 110.131,163.322 110.439,163.322 110.668,163.551 110.668,164.77 110.871,164.973 111.303,164.973 111.506,164.77 111.506,164.304 111.658,164.152 112.057,164.152 112.319,164.414 112.319,164.694 112.598,164.973 113.716,164.973 113.894,165.151 113.894,165.405 113.995,165.506 114.503,165.506 114.732,165.735 115.621,165.735 115.748,165.608 115.748,165.43 115.646,165.329 114.884,165.329 113.5,163.944 v3(113.5,163.735)
  GND02 w0.102: v2(108.065,158.965) v1(108.465,159.365)
ADDR3-D23: U1.U3 U8.H7 | length 18.5
  Top Layer w0.114: v2(108.065,158.165) v1(108.465,157.765) ; v3(113.5,166.935) U8.H7@113.9,167.335
  ART10 w0.109: v1(108.465,157.765) 108.275,157.765 107.899,158.14 107.518,158.14 107.29,158.369 107.29,159.537 107.493,159.741 107.899,159.741 108.052,159.893 108.052,160.02 107.95,160.122 107.671,160.122 107.569,160.223 107.569,160.426 107.671,160.528 108.179,160.528 108.306,160.655 108.306,161.16 108.195,161.271 107.972,161.271 107.861,161.381 107.861,161.529 107.972,161.639 108.195,161.639 108.306,161.75 108.306,161.897 108.195,162.008 107.972,162.008 107.861,162.118 107.861,162.265 107.972,162.376 108.195,162.376 108.306,162.486 108.306,163.17 108.483,163.347 108.864,163.347 109.118,163.601 109.118,164.77 109.347,164.998 109.677,164.998 110.211,165.532 110.668,165.532 112.471,167.335 113.1,167.335 v3(113.5,166.935)
  GND02 w0.109: v2(108.065,158.165) v1(108.465,157.765)
ADDR3-D24: U1.V1 U8.D7 | length 19.7
  Top Layer w0.114: v2(105.855,160.325) 106.16,160.63 106.756,160.63 107.665,159.721 U1.V1@107.665,159.365
  Top Layer w0.254: v3(110.3,166.935) U8.D7@110.7,167.335
  ART05 w0.109: v1(105.287,161.786) 105.613,162.112 105.613,163.551 106.169,164.107 106.169,164.411 105.423,165.158 105.423,165.341 105.545,165.463 105.728,165.463 106.269,164.923 106.452,164.923 106.574,165.045 106.574,165.228 106.033,165.768 106.033,165.952 106.156,166.074 106.339,166.074 106.957,165.456 107.112,165.456 107.239,165.583 107.239,165.784 106.644,166.379 106.644,166.562 106.858,166.776 107.137,166.776 107.77,166.144 107.952,166.144 108.052,166.243 108.052,166.472 108.28,166.7 108.28,167.208 108.407,167.335 109.9,167.335 v3(110.3,166.935)
  GND02 w0.102: v1(105.287,161.786) 105.287,160.894 v2(105.855,160.325)
ADDR3-D25: U1.Y3 U8.C3 | length 19.6
  Top Layer w0.114: v2(105.665,158.165) U1.Y3@106.065,157.765 ; U8.C3@109.9,164.135 v3(110.3,164.535)
  ART05 w0.109: v1(105.265,157.765) 105.391,157.765 105.817,158.191 106.197,158.191 106.426,157.963 106.426,157.917 106.427,157.916 106.427,157.619 106.187,157.378 105.918,157.378 105.664,157.124 105.664,156.007 105.867,155.804 105.915,155.804 ; 105.915,155.803 106.781,155.803 107.518,156.54 108.661,156.54 108.903,156.782 108.903,157.251 109.03,157.378 109.499,157.378 109.677,157.556 109.677,159.334 110.033,159.69 110.033,160.198 109.906,160.325 109.601,160.325 109.449,160.477 109.449,160.604 109.601,160.757 109.906,160.757 110.033,160.884 110.033,161.138 109.88,161.29 109.576,161.29 109.423,161.442 109.423,161.595 109.525,161.696 109.779,161.696 109.906,161.823 109.906,164.141 v3(110.3,164.535)
  GND02 w0.109: v1(105.265,157.765) v2(105.665,158.165)
ADDR3-D26: U1.W1 U8.C8 | length 19.4
  Top Layer w0.114: v2(106.465,159.765) U1.W1@106.865,159.365
  Top Layer w0.254: U8.C8@109.9,168.135 v3(110.3,167.735)
  ART05 w0.109: v1(105.265,160.219) 104.837,159.791 104.115,159.791 103.937,159.969 103.937,160.68 103.759,160.858 103.759,162.408 104.318,162.966 104.318,166.624 104.826,167.132 105.054,167.132 105.334,166.853 105.512,166.853 105.664,167.005 105.664,167.259 105.461,167.462 105.461,167.767 106.248,168.554 106.477,168.554 106.705,168.326 106.883,168.326 107.112,168.554 107.315,168.554 107.696,168.173 109.862,168.173 v3(110.3,167.735)
  GND02 w0.102: v1(105.265,160.219) 105.265,160.069 105.569,159.765 v2(106.465,159.765)
ADDR3-D27: U1.Y4 U8.C2 | length 19.6
  Top Layer w0.114: v2(105.665,157.365) U1.Y4@106.065,156.965 ; U8.C2@109.9,163.335 v3(110.3,162.935)
  ART05 w0.109: v1(105.265,156.965) 104.953,156.653 104.953,155.321 105.308,154.965 106.197,154.965 106.578,155.346 107.086,155.346 107.493,155.753 108.565,155.753 109.377,156.566 110.261,156.566 110.465,156.769 110.465,159.827 110.594,159.957 111.161,159.957 111.29,160.086 111.29,160.259 111.161,160.388 110.478,160.388 110.348,160.518 110.348,160.691 110.478,160.82 111.161,160.82 111.29,160.95 111.29,161.122 111.161,161.252 110.426,161.252 110.236,161.442 110.236,161.595 110.363,161.722 110.541,161.722 110.693,161.874 110.693,162.542 v3(110.3,162.935)
  GND02 w0.109: v1(105.265,156.965) v2(105.665,157.365)
ADDR3-D28: U1.Y2 U8.A7 | length 19.5
  Top Layer w0.114: v2(105.665,158.965) U1.Y2@106.065,158.565
  Top Layer w0.254: v3(107.9,166.935) U8.A7@108.3,167.335
  ART05 w0.109: v1(105.265,158.565) 105.639,158.939 105.639,160.731 105.461,160.909 105.029,160.909 104.864,161.074 104.864,162.24 104.734,162.369 104.61,162.369 104.481,162.499 104.481,162.672 104.534,162.725 104.61,162.801 105.179,162.801 105.308,162.931 105.308,163.104 105.179,163.233 104.739,163.233 104.61,163.363 104.61,163.535 104.739,163.665 105.179,163.665 105.308,163.794 105.308,163.967 105.179,164.097 104.739,164.097 104.61,164.226 104.61,164.399 104.739,164.528 105.179,164.528 105.308,164.658 105.308,164.831 105.179,164.96 104.788,164.96 104.623,165.125 104.623,165.76 104.75,165.887 105.283,165.887 106.02,166.624 106.02,167.64 106.172,167.792 106.35,167.792 106.477,167.665 106.477,167.208 106.578,167.107 106.782,167.107 106.959,167.284 106.959,167.665 107.086,167.792 107.34,167.792 107.493,167.64 107.493,167.342 v3(107.9,166.935)
  GND02 w0.109: v1(105.265,158.565) v2(105.665,158.965)
ADDR3-D29: U1.W3 U8.A2 | length 19.6
  Top Layer w0.114: v2(106.465,158.165) U1.W3@106.865,157.765 ; v3@106.502,163.728 v3(106.515,163.728) 106.908,163.335 U8.A2@108.3,163.335
  ART05 w0.109: v1(106.065,157.765) 105.873,157.765 105.435,157.328 104.191,157.328 103.988,157.124 103.988,156.54 103.759,156.312 103.175,156.312 102.946,156.54 102.946,156.972 103.53,157.556 103.53,157.81 103.302,158.039 102.895,158.039 102.641,158.293 102.641,158.598 103.048,159.004 103.53,159.004 103.886,158.648 103.886,158.318 104.038,158.166 105.378,158.166 105.893,158.681 105.893,163.119 v3@106.502,163.728
  GND02 w0.102: v1(106.065,157.765) v2(106.465,158.165)
ADDR3-D30: U1.V2 U8.B8 | length 19.6
  Top Layer w0.114: v2(107.265,158.965) U1.V2@107.665,158.565 ; U8.B8@109.1,168.135 v3(109.5,168.535)
  ART05 w0.109: v1(105.265,159.365) 104.853,158.953 104.038,158.953 103.683,159.309 103.683,160.475 103.48,160.678 103.48,162.611 104.024,163.155 104.024,166.914 106.045,168.935 109.1,168.935 v3(109.5,168.535)
  GND02 w0.102: v1(105.265,159.365) 106.865,159.365 v2(107.265,158.965)
ADDR3-D31: U1.V3 U8.A3 | length 19.4
  Top Layer w0.114: v2(107.265,158.165) v1(107.665,157.765) ; v3(107.9,163.735) U8.A3@108.3,164.135
  ART05 w0.109: v1(107.665,157.765) 108.066,158.166 108.661,158.166 108.864,158.369 108.864,158.75 108.661,158.953 107.493,158.953 107.303,159.143 107.303,160.084 107.442,160.223 107.62,160.223 107.925,159.918 109.017,159.918 109.195,160.096 109.195,160.299 109.08,160.414 108.056,160.414 107.927,160.543 107.927,160.716 108.056,160.845 109.106,160.845 109.22,160.96 109.22,161.138 109.08,161.277 107.85,161.277 107.72,161.407 107.72,161.58 107.85,161.709 108.176,161.709 108.306,161.839 108.306,162.011 108.176,162.141 107.43,162.141 107.3,162.27 107.3,162.443 107.43,162.573 108.953,162.573 109.118,162.738 109.118,163.195 108.966,163.347 108.288,163.347 v3(107.9,163.735)
  GND02 w0.102: v2(107.265,158.165) v1(107.665,157.765)
ADDR3-DM0: RR2.6 U1.A1 U6.E7 | length 33.6
  Top Layer w0.114: U1.A1@121.265,159.365 v2(121.665,159.765)
  ART05 w0.109: v3(111.1,164.535) 111.1,164.287 112.293,163.093 112.293,161.773 115.315,158.751 115.315,158.014 115.875,157.455 117.348,157.455 117.653,157.15 117.653,156.794 117.881,156.566 119.837,156.566 120.091,156.82 120.091,157.15 120.294,157.353 121.437,157.353 121.691,157.607 121.691,158.775 122.065,159.149 v1(122.065,159.365)
  GND02 w0.109: v2(121.665,159.765) v1(122.065,159.365)
  Bottom Layer w0.114: U6.E7@111.5,164.135 v3(111.1,164.535) 111.506,164.941 112.465,164.941 113.335,165.811 113.69,165.811 114.605,164.897 122.301,164.897 122.729,164.469 123.325,164.469 RR2.6@123.96,164.469
ADDR3-DM1: RR2.8 U1.F1 U6.D3 | length 31.3
  Top Layer w0.114: U1.F1@117.265,159.365 v5(117.665,159.765)
  ART03 w0.102: v3(111.1,166.935) 110.852,166.935 110.541,166.624 110.541,166.497 110.642,166.395 111.277,166.395 111.404,166.268 111.404,165.329 111.735,164.998 112.192,164.998 112.319,165.125 112.319,165.608 112.497,165.786 112.928,165.786 113.081,165.633 113.081,164.287 113.259,164.109 113.716,164.109 113.856,163.97 113.856,163.538 114.021,163.373 114.478,163.373 114.681,163.17 114.681,162.484 114.783,162.382 114.986,162.382 115.113,162.509 115.113,162.916 115.291,163.093 116.586,163.093 116.738,162.941 116.738,161.594 116.953,161.379 117.157,161.379 117.475,161.061 117.983,161.061 118.11,160.934 118.11,160.731 117.958,160.579 117.817,160.579 117.665,160.426 v5(117.665,159.765)
  Bottom Layer w0.114: U6.D3@110.7,167.335 v3(111.1,166.935) 111.487,166.548 114.554,166.548 115.418,165.684 122.555,165.684 122.75,165.489 123.325,165.489 RR2.8@123.96,165.489
ADDR3-DM2: RR2.7 U1.T1 U8.E7 | length 32.9
  Top Layer w0.114: v2(108.865,159.765) U1.T1@109.265,159.365 ; v3(110.3,166.184) 111.1,166.184 111.5,166.584 U8.E7@111.5,167.335
  ART10 w0.109: v1(106.909,160.096) 106.506,160.499 106.506,161.166 106.731,161.392 107.036,161.392 107.264,161.62 107.264,161.95 106.985,162.23 106.985,164.059 107.274,164.348 107.274,164.531 106.829,164.977 106.829,165.16 106.951,165.282 107.134,165.282 107.58,164.837 107.763,164.837 107.885,164.959 107.885,165.142 107.44,165.587 107.44,165.771 107.562,165.893 107.745,165.893 108.19,165.447 108.373,165.447 108.496,165.569 108.496,165.753 108.05,166.198 108.05,166.381 108.172,166.503 108.356,166.503 108.801,166.058 108.984,166.058 109.449,166.522 109.962,166.522 v3(110.3,166.184)
  GND02 w0.102: v1(106.909,160.096) 106.948,160.057 108.573,160.057 v2(108.865,159.765)
  Bottom Layer w0.114: v3(110.3,166.184) 110.698,165.786 112.852,165.786 113.208,166.141 113.817,166.141 114.732,165.227 122.428,165.227 122.686,164.969 123.325,164.969 RR2.7@123.96,164.969
ADDR3-DM3: RR5.8 U1.Y1 U8.D3 | length 41.1
  Top Layer w0.114: U1.Y1@106.065,159.365 106.065,159.925 v2(106.465,160.325) ; v3(110.3,163.735) U8.D3@110.7,164.135
  ART05 w0.109: v1(106.865,160.96) 107.264,161.359 107.264,161.925 106.959,162.23 106.959,162.585 107.493,163.119 107.493,163.906 107.721,164.135 108.153,164.135 108.306,164.287 108.306,164.922 108.555,165.172 108.738,165.172 108.963,164.947 109.146,164.947 109.268,165.069 109.268,165.252 109.107,165.414 109.029,165.492 109.029,165.675 109.151,165.797 109.334,165.797 109.929,165.202 110.287,165.202 110.515,165.43 110.515,165.659 110.388,165.786 109.956,165.786 109.654,166.088 109.654,166.271 109.957,166.573 110.15,166.573 110.541,166.573 110.719,166.751 110.719,167.208 110.846,167.335 111.328,167.335 111.481,167.183 111.481,166.497 111.15,166.167 111.15,165.227 110.662,164.739 110.662,164.097 v3(110.3,163.735)
  ART12 w0.102: v3(110.3,163.735) 109.906,164.129 109.906,169.57 110.49,170.155 120.828,170.155 121.59,169.393 121.59,168.58 122.395,167.775 v8(123.325,167.775)
  GND02 w0.102: v2(106.465,160.325) 106.465,160.56 v1(106.865,160.96)
  Bottom Layer w0.114: v8(123.325,167.775) RR5.8@123.96,167.775
ADDR3-DQS0_N: U1.B2 U6.G3 | length 19.4
  Top Layer w0.089: U1.B2@120.465,158.565 v2(120.865,158.965)
  ART05 w0.099: v3(113.5,167.735) 113.5,167.475 113.894,167.081 113.894,165.913 114.046,165.76 114.848,165.76 115.039,165.951 115.039,166.115 115.342,166.418 115.865,166.418 116.154,166.129 116.154,165.887 116.284,165.758 117.615,165.758 118.034,165.339 118.034,164.033 118.341,163.726 121.081,163.726 122.07,162.737 122.07,161.745 121.387,161.061 121.387,159.893 121.641,159.639 121.641,159.182 121.265,158.806 v1(121.265,158.565)
  GND02 w0.109: v2(120.865,158.965) v1(121.265,158.565)
  Bottom Layer w0.089: U6.G3@113.1,167.335 v3(113.5,167.735)
ADDR3-DQS0_P: U1.C2 U6.F3 | length 19.5
  Top Layer w0.089: U1.C2@119.665,158.565 v2(120.065,158.965)
  ART05 w0.099: v3(112.7,166.935) 112.795,167.03 113.055,167.03 113.144,166.941 113.144,166.687 113.259,166.573 113.487,166.573 113.614,166.446 113.617,166.446 113.617,165.798 113.931,165.484 114.963,165.484 115.316,165.837 115.316,166 115.457,166.141 115.75,166.141 115.877,166.014 115.877,165.773 116.169,165.481 117.5,165.481 117.757,165.224 117.757,163.919 118.226,163.449 120.966,163.449 121.793,162.622 121.793,161.859 121.11,161.176 121.11,159.896 120.833,159.619 120.833,158.73 120.668,158.565 v1(120.465,158.565)
  GND02 w0.109: v2(120.065,158.965) v1(120.465,158.565)
  Bottom Layer w0.089: U6.F3@112.3,167.335 v3(112.7,166.935)
ADDR3-DQS1_N: U1.F2 U6.B7 | length 17.8
  Top Layer w0.089: U1.F2@117.265,158.565 v5(117.665,158.965)
  ART03 w0.097: v3(109.5,164.535) 109.398,164.637 109.398,165.521 109.688,165.811 110.707,165.811 110.973,165.546 110.973,165.049 111.074,164.948 111.328,164.948 111.506,164.77 111.506,164.338 111.785,164.059 111.785,163.5 111.912,163.373 112.116,163.373 112.293,163.195 112.293,162.842 112.576,162.56 112.903,162.56 113.055,162.408 113.589,162.408 113.947,162.049 113.947,161.872 114.071,161.747 114.365,161.747 114.63,161.482 114.63,161.265 114.783,161.112 115.087,161.112 115.214,161.239 115.214,161.888 115.505,162.179 116.016,162.179 116.307,161.888 116.307,161.468 116.916,160.858 116.916,160.463 116.713,160.26 116.713,160.147 117.405,159.455 117.887,159.455 118.034,159.309 118.034,159.106 117.893,158.965 v5(117.665,158.965) v5@117.596,158.965
  Bottom Layer w0.089: U6.B7@109.1,164.135 v3(109.5,164.535)
ADDR3-DQS1_P: U1.G2 U6.C7 | length 17.8
  Top Layer w0.089: U1.G2@116.465,158.565 v5(116.865,158.965)
  ART03 w0.097: v3(109.5,163.735) 109.934,164.169 109.934,164.719 109.677,164.976 109.677,165.405 109.804,165.532 110.592,165.532 110.693,165.43 110.693,164.338 110.943,164.088 111.35,164.088 111.506,163.932 111.506,162.763 111.684,162.585 111.75,162.585 111.754,162.582 112.094,162.582 112.293,162.382 112.293,162.042 112.554,161.782 112.862,161.782 113.157,162.077 113.524,162.077 113.668,161.934 113.668,161.756 113.956,161.468 114.249,161.468 114.351,161.366 114.351,161.149 114.667,160.833 115.203,160.833 115.494,161.123 115.494,161.773 115.621,161.9 115.9,161.9 116.027,161.773 116.027,161.352 116.611,160.768 116.611,160.553 116.434,160.376 116.434,160.031 117.125,159.34 117.125,159.225 v5(116.865,158.965)
  Bottom Layer w0.089: v3(109.5,163.735) U6.C7@109.9,164.135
